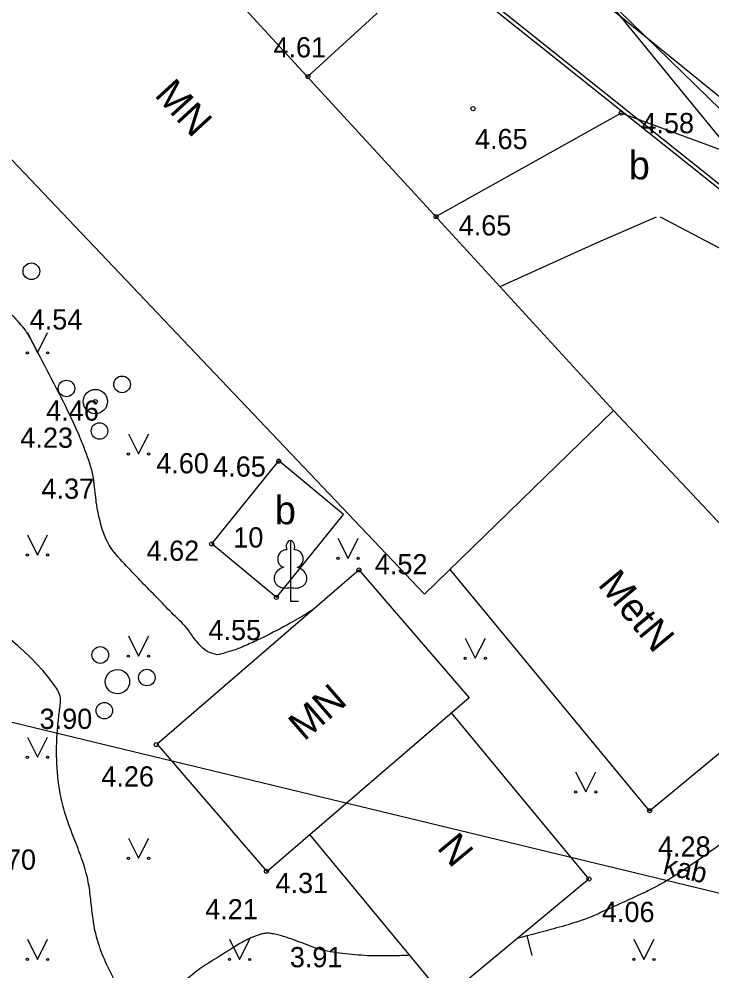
# Model space of a CAD drawing. Extents: x 519536 to 519949, y 326041 to 326519.
# Drawn here: x 519767.04 to 519784.18, y 326282.21 to 326305.75 of the extents above; entities that cross this region are included whole.
import ezdxf

# ---------------------------------------------------------------- set-up
doc = ezdxf.new("R2010")
doc.units = 0
for name, color, linetype in [('APGR_SARK_####_####_#', 7, 'Continuous'), ('BUVE_EKAS_####_####_#', 7, 'Continuous'), ('BUVE_EKAS_BPAL_####_#', 7, 'Continuous'), ('BUVE_EKAS_RAKS_TKST_#', 7, 'Continuous'), ('CELI_CMAL_####_####_#', 7, 'Continuous'), ('CELI_CSEG_####_TKST_#', 7, 'Continuous'), ('ELEK_VADP_ZSPR_####_#', 7, 'Continuous'), ('RELJ_AATZ_####_TKST_#', 7, 'Continuous'), ('RELJ_ELEM_####_####_#', 7, 'Continuous'), ('RELJ_HORZ_PAMT_####_#', 7, 'Continuous'), ('ROBZ_PROJ_####_####_#', 7, 'Continuous'), ('ROBZ_UZMR_####_####_#', 7, 'Continuous'), ('SAKK_KKAN_####_####_#', 7, 'Continuous'), ('SAKT_VADV_PKAB_####_#', 7, 'Continuous'), ('SAKT_VADV_PKAB_TKST_#', 7, 'Continuous'), ('TERT_DIAM_####_TKST_#', 7, 'Continuous'), ('TERT_ELEM_####_####_#', 7, 'Continuous')]:
    doc.layers.add(name, color=color, linetype=linetype)

msp = doc.modelspace()

# ---------------------------------------------------------------- linework, layer by layer
at = {"layer": 'APGR_SARK_####_####_#'}
msp.add_line((519771.5020408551, 326318.57686486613), (519839.50526056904, 326235.2628850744), dxfattribs=at)
at = {"layer": 'BUVE_EKAS_####_####_#'}
for p, q in [((519777.119, 326301.12), (519768.47500000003, 326310.543)), ((519781.74700000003, 326296.075), (519777.119, 326301.12)), ((519781.74700000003, 326296.075), (519780.3550036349, 326294.7205526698)), ((519784.831, 326292.793), (519781.74700000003, 326296.075)), ((519780.3550036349, 326294.7205526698), (519777.076, 326291.53)), ((519770.462, 326287.832), (519775.4511530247, 326292.13029778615)), ((519775.4511530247, 326292.13029778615), (519778.1731530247, 326288.9702977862)), ((519778.1731530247, 326288.9702977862), (519773.184, 326284.672)), ((519773.184, 326284.672), (519770.462, 326287.832))]:
    msp.add_line(p, q, dxfattribs=at)
msp.add_lwpolyline([(519777.076, 326291.53), (519763.07800000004, 326306.251)], dxfattribs=at)
at = {"layer": 'BUVE_EKAS_BPAL_####_#'}
for p, q in [((519782.641, 326286.17600000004), (519777.7031957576, 326292.1402771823)), ((519782.641, 326286.17600000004), (519787.2223480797, 326289.96888215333)), ((519781.13800000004, 326284.489), (519777.73818964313, 326288.5955644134)), ((519777.58200000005, 326281.54500000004), (519774.23402478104, 326285.58895376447)), ((519777.58200000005, 326281.54500000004), (519781.13800000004, 326284.489))]:
    msp.add_line(p, q, dxfattribs=at)
at = {"layer": 'CELI_CMAL_####_####_#'}
for p, q in [((519775.9, 326305.89900000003), (519774.189, 326304.33300000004)), ((519771.808, 326292.775), (519773.47021137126, 326294.8259624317)), ((519775.07021137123, 326293.50296243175), (519773.47021137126, 326294.8259624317)), ((519773.408, 326291.452), (519775.07021137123, 326293.50296243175)), ((519773.408, 326291.452), (519771.808, 326292.775))]:
    msp.add_line(p, q, dxfattribs=at)
for points in [[(519782.901, 326300.86100000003), (519784.67600000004, 326299.934), (519785.84400000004, 326301.988), (519781.93700000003, 326303.43100000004), (519777.358, 326300.87)], [(519778.94100000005, 326299.141), (519781.308, 326300.216), (519782.81100000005, 326300.865)]]:
    msp.add_lwpolyline(points, dxfattribs=at)
at = {"layer": 'ELEK_VADP_ZSPR_####_#'}
for points in [[(519830.368663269, 326246.030227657), (519828.1702429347, 326249.1807123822), (519802.20740225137, 326283.8956003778), (519795.9928819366, 326292.28332314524), (519770.740641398, 326312.4157499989), (519767.54869624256, 326319.6985019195), (519768.2034511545, 326324.3475465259), (519772.3174717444, 326338.8567057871)], [(519780.782, 326304.525), (519771.889, 326311.62200000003)], [(519799.34857528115, 326287.9422010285), (519796.069, 326292.32800000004), (519780.782, 326304.525)]]:
    msp.add_lwpolyline(points, dxfattribs=at)
at = {"layer": 'RELJ_ELEM_####_####_#'}
for centre in [(519774.189, 326304.33300000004), (519778.2711320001, 326303.53878600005), (519781.93700000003, 326303.43100000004), (519777.358, 326300.87), (519768.93000000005, 326296.29600000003), (519773.467, 326294.82200000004), (519771.808, 326292.775), (519775.451, 326292.13), (519773.408, 326291.452), (519770.43700000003, 326287.81200000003), (519782.641, 326286.17600000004), (519773.161, 326284.68), (519781.13800000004, 326284.489)]:
    msp.add_circle(centre, 0.05, dxfattribs=at)
at = {"layer": 'RELJ_HORZ_PAMT_####_#'}
msp.add_line((519779.6058604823, 326283.08196167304), (519779.7280805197, 326282.5971294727), dxfattribs=at)
for points in [[(519768.9482272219, 326293.8646011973), (519768.92128528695, 326294.1106640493), (519768.88297060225, 326294.40952680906), (519768.81333221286, 326294.7013025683), (519768.7033955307, 326295.02040492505), (519768.58319504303, 326295.3343539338), (519768.3089513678, 326295.94770706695), (519767.3925420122, 326297.7320684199), (519767.26196401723, 326297.96806334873), (519767.13499731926, 326298.1455611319), (519766.9909414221, 326298.30928763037), (519766.6741187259, 326298.6102247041), (519766.4738319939, 326298.78710908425), (519766.27167638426, 326298.9603092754), (519765.84971994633, 326299.2824635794), (519764.96896151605, 326299.87938607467), (519764.0832520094, 326300.48417170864), (519763.6505364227, 326300.81361992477), (519763.4447373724, 326300.9927193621), (519763.244, 326301.18), (519762.8425471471, 326301.6241986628), (519762.4992198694, 326302.1146140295), (519762.21454526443, 326302.63803209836), (519761.9836765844, 326303.19307164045), (519761.83115030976, 326303.7023842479), (519761.73341554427, 326304.22113132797), (519761.63275072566, 326305.2671582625), (519761.6394282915, 326305.79893731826), (519761.6535327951, 326306.33087839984), (519761.70018845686, 326307.3942862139), (519761.71876058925, 326307.74637150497)], [(519771.93279070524, 326290.03450955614), (519771.6304535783, 326290.16122137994), (519771.50148263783, 326290.2901018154), (519771.3838236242, 326290.42711000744), (519771.2329594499, 326290.6383997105), (519770.867915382, 326291.0229712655), (519770.49724409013, 326291.4029522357), (519770.1258703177, 326291.7828749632), (519769.75871880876, 326292.16727179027), (519769.3417415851, 326292.6437591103), (519769.21924065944, 326292.8447509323), (519769.1290083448, 326293.060317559), (519769.00844141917, 326293.5134353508), (519768.95440073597, 326293.8101537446), (519768.9482272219, 326293.8646011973)], [(519772.3037991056, 326282.7687551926), (519771.7265414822, 326282.40449786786), (519771.5247364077, 326282.2736022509), (519771.32577707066, 326282.12007177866), (519770.9351707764, 326281.7904900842), (519770.3629491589, 326281.4100049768), (519770.26868459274, 326281.37807846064), (519770.1746338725, 326281.3589304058), (519769.80530474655, 326281.4817614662), (519769.4797521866, 326281.86503770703), (519769.21033155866, 326282.3790786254), (519769.00939822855, 326282.8942037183), (519768.8999230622, 326283.3288329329), (519768.84078488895, 326283.7662808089), (519768.79052642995, 326284.20120891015), (519768.70769040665, 326284.6282788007), (519768.5479745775, 326285.1197754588), (519768.36125570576, 326285.6060716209), (519768.1861727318, 326286.0971767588), (519768.06136459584, 326286.60310034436), (519768.00299225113, 326288.2795758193), (519768.04188478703, 326288.62647923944), (519768.06447333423, 326288.79963326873), (519768.0680781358, 326288.97267270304), (519767.9178786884, 326289.2775001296), (519765.26791854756, 326291.6173466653), (519765.17379177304, 326291.6835162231), (519764.88886906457, 326291.7177816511), (519764.5102364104, 326291.0977889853), (519763.1472943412, 326287.19180446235), (519763.086313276, 326286.0097349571), (519763.4077698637, 326284.9752966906), (519763.89341618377, 326283.4690026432), (519764.06192513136, 326282.7101966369), (519764.0542015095, 326281.93201949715), (519763.80013137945, 326281.1633634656), (519763.55880576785, 326280.79163469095), (519763.40573596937, 326280.6105001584), (519763.32062002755, 326280.52131286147), (519763.22960080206, 326280.4331207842), (519762.8743324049, 326280.22632388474), (519762.51153899, 326280.1989100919), (519761.7900461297, 326280.3313768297), (519761.59721181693, 326280.3721994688), (519761.40436009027, 326280.4318008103), (519761.21165912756, 326280.48302410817), (519761.0192771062, 326280.4987126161), (519759.23806750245, 326279.99160951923), (519758.9520704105, 326279.8355438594), (519758.68201619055, 326279.66972863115), (519758.41540199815, 326279.5052413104), (519758.13972498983, 326279.3531593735), (519756.45872597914, 326278.5629404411), (519754.74648434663, 326277.84880748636), (519754.5322637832, 326277.79851086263), (519754.0413100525, 326277.46207363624), (519753.6762339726, 326277.0319883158), (519753.3405213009, 326276.59453688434), (519752.75223708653, 326275.69236061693), (519752.2665592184, 326274.7451946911), (519751.8735895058, 326273.74268896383), (519751.57436674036, 326272.7572303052), (519751.3630077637, 326271.755380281), (519751.1902698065, 326270.21862873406)], [(519774.30212140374, 326291.1403742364), (519774.20817665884, 326291.0841860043), (519773.9803627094, 326290.94690071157), (519773.74973964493, 326290.81407985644), (519773.0794785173, 326290.4615372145), (519772.73671818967, 326290.3007069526), (519772.56252624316, 326290.22564805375), (519772.3861152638, 326290.1547298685), (519772.1596644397, 326290.0861544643), (519771.93323377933, 326290.03452825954), (519771.93279070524, 326290.03450955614)], [(519786.2017961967, 326286.52632436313), (519786.09832418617, 326286.4692661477), (519785.99075401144, 326286.41957294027), (519785.88364397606, 326286.36927084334), (519785.78155238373, 326286.3103859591), (519785.2662393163, 326285.9585843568), (519784.79090867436, 326285.6261180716), (519784.3176832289, 326285.2908254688), (519783.60357046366, 326284.79307712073), (519783.48329929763, 326284.7116862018), (519783.3625137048, 326284.6309428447), (519782.98794787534, 326284.4028738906), (519782.5996328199, 326284.1988032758), (519782.2030383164, 326284.010043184), (519781.8036341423, 326283.82790579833), (519781.5408067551, 326283.7084944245), (519781.3163471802, 326283.60582770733), (519780.19742068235, 326283.23858751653), (519779.36156973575, 326283.0182995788)], [(519776.7062727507, 326282.60277381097), (519776.5027566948, 326282.5941124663), (519776.299135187, 326282.58865602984), (519776.09554168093, 326282.5859240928), (519775.89210963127, 326282.5854362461), (519775.5830794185, 326282.59642601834), (519775.2741894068, 326282.62150404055), (519774.9687310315, 326282.65571572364), (519774.66504914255, 326282.70404220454), (519774.41456953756, 326282.76814304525), (519774.16767239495, 326282.8578403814), (519773.9213618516, 326282.95419523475), (519773.6726420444, 326283.03826862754), (519773.54126718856, 326283.07933466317), (519773.4087875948, 326283.1150522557), (519773.2760518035, 326283.13944821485), (519773.20985300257, 326283.14553395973), (519773.1768422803, 326283.14672211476), (519773.1439083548, 326283.14654934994), (519773.050292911, 326283.1305543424), (519772.9572017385, 326283.0997170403), (519772.86462869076, 326283.06717382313), (519772.7748411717, 326283.0298551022), (519772.68411011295, 326282.98580293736), (519772.59450583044, 326282.9401070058), (519772.41991509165, 326282.8408592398), (519772.3037991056, 326282.7687551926)]]:
    msp.add_spline(points, degree=3, dxfattribs=at)
at = {"layer": 'ROBZ_PROJ_####_####_#'}
msp.add_line((519793.42600000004, 326294.6769999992), (519766.63399999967, 326320.8839999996), dxfattribs=at)
at = {"layer": 'ROBZ_UZMR_####_####_#'}
msp.add_line((519766.63399999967, 326320.8839999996), (519793.42600000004, 326294.6769999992), dxfattribs=at)
at = {"layer": 'SAKK_KKAN_####_####_#'}
for p, q in [((519773.07, 326313.014), (519782.058, 326305.712)), ((519782.058, 326305.712), (519794.06700000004, 326295.955))]:
    msp.add_line(p, q, dxfattribs=at)
at = {"layer": 'SAKT_VADV_PKAB_####_#'}
msp.add_lwpolyline([(519822.5716386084, 326274.90377568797), (519730.8236856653, 326297.05955857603)], dxfattribs=at)
at = {"layer": 'TERT_ELEM_####_####_#'}
for p, q in [((519767.25, 326298), (519767.5, 326297.5)), ((519767.5, 326297.5), (519767.75, 326298)), ((519769.75, 326295.5), (519770, 326295)), ((519770, 326295), (519770.25, 326295.5)), ((519767.25, 326293), (519767.5, 326292.5)), ((519767.5, 326292.5), (519767.75, 326293)), ((519774.9314085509, 326292.91795918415), (519775.1814085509, 326292.41795918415)), ((519775.1814085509, 326292.41795918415), (519775.4314085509, 326292.91795918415)), ((519773.75700000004, 326291.7049923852), (519773.75700000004, 326291.358)), ((519773.75700000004, 326291.358), (519773.95700000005, 326291.358)), ((519769.75, 326290.5), (519770, 326290)), ((519770, 326290), (519770.25, 326290.5)), ((519778.0786365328, 326290.4481587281), (519778.3286365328, 326289.9481587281)), ((519778.3286365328, 326289.9481587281), (519778.5786365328, 326290.4481587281)), ((519767.25, 326288), (519767.5, 326287.5)), ((519767.5, 326287.5), (519767.75, 326288)), ((519780.8082180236, 326287.14139886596), (519781.0582180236, 326286.64139886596)), ((519781.0582180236, 326286.64139886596), (519781.3082180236, 326287.14139886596)), ((519769.75, 326285.5), (519770, 326285)), ((519770, 326285), (519770.25, 326285.5)), ((519767.25, 326283), (519767.5, 326282.5)), ((519767.5, 326282.5), (519767.75, 326283)), ((519772.25, 326283), (519772.5, 326282.5)), ((519772.5, 326282.5), (519772.75, 326283)), ((519782.25, 326283), (519782.5, 326282.5)), ((519782.5, 326282.5), (519782.75, 326283))]:
    msp.add_line(p, q, dxfattribs=at)
for points in [[(519773.75700000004, 326292.8579988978), (519773.75700000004, 326291.7049923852)], [(519773.84655848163, 326292.6256060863), (519773.8455632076, 326292.626518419)]]:
    msp.add_lwpolyline(points, dxfattribs=at)
for centre, radius in [((519767.34848458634, 326299.51684871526), 0.2066127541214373), ((519767.2497200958, 326297.49954969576), 0.02800000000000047), ((519767.7497200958, 326297.49954969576), 0.02630589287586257), ((519769.59148458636, 326296.7208487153), 0.2066127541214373), ((519768.21586157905, 326296.61984797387), 0.20413472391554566), ((519768.93000000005, 326296.29600000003), 0.3006396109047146), ((519769.03329362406, 326295.56845055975), 0.20454262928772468), ((519769.7497200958, 326294.99954969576), 0.02800000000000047), ((519770.2497200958, 326294.99954969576), 0.02630589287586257), ((519767.2497200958, 326292.49954969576), 0.02800000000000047), ((519767.7497200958, 326292.49954969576), 0.02630589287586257), ((519774.9311286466, 326292.41750887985), 0.02800000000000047), ((519775.4311286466, 326292.41750887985), 0.02630589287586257), ((519769.0531512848, 326290.02848458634), 0.2066127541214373), ((519769.7497200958, 326289.99954969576), 0.02800000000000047), ((519770.2497200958, 326289.99954969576), 0.02630589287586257), ((519778.07835662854, 326289.94770842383), 0.02800000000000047), ((519778.57835662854, 326289.94770842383), 0.02630589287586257), ((519769.478, 326289.367), 0.3006396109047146), ((519770.2055494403, 326289.47029362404), 0.20454262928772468), ((519769.1541520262, 326288.65286157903), 0.20413472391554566), ((519767.2497200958, 326287.49954969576), 0.02800000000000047), ((519767.7497200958, 326287.49954969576), 0.02630589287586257), ((519780.80793811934, 326286.64094856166), 0.02800000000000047), ((519781.30793811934, 326286.64094856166), 0.02630589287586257), ((519769.7497200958, 326284.99954969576), 0.02800000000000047), ((519770.2497200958, 326284.99954969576), 0.02630589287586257), ((519767.2497200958, 326282.49954969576), 0.02800000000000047), ((519767.7497200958, 326282.49954969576), 0.02630589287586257), ((519772.2497200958, 326282.49954969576), 0.02800000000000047), ((519772.7497200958, 326282.49954969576), 0.02630589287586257), ((519782.2497200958, 326282.49954969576), 0.02800000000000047), ((519782.7497200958, 326282.49954969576), 0.02630589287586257)]:
    msp.add_circle(centre, radius, dxfattribs=at)
for centre, major_axis, ratio, start_param, end_param in [((519773.75740043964, 326292.7080684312), (-2.411082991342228e-17, -0.1499315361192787), 0.7071067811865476, 3.1453697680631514, 5.287484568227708), ((519773.7565995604, 326292.7080684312), (4.2472147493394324e-17, -0.1499315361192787), 0.7071067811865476, 0.9957007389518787, 3.137815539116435), ((519773.6287092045, 326292.4132030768), (-0.03873231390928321, -0.21240300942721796), 0.8613228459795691, 3.141592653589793, 6.283185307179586), ((519773.88529079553, 326292.4132030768), (0.038732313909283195, -0.21240300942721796), 0.8613228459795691, 0, 3.141592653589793), ((519773.66744151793, 326291.95091417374), (0.306817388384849, 0.0951133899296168), 0.8144450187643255, 1.5707963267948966, 4.752014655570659), ((519773.8465584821, 326291.95091417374), (-0.30681738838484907, 0.09511338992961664), 0.8144450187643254, 1.5311706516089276, 4.71238898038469)]:
    msp.add_ellipse(centre, major_axis=major_axis, ratio=ratio, start_param=start_param, end_param=end_param, dxfattribs=at)

# ---------------------------------------------------------------- texts
at = {"layer": 'BUVE_EKAS_RAKS_TKST_#'}
for s, rotation, p in [('MN', 312.5310907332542, (519770.37162944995, 326303.8638410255)), ('MetN', 309.6212388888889, (519781.33878672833, 326291.7645908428)), ('MN', 40.95065555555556, (519774.09500000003, 326287.88300000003)), ('N', 309.6212388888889, (519777.359, 326285.25200000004))]:
    msp.add_text(s, height=0.7, rotation=rotation, dxfattribs=at).set_placement(p)
at = {"layer": 'CELI_CSEG_####_TKST_#'}
for p in [(519782.12475356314, 326301.79174366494), (519773.3697045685, 326293.26138256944)]:
    msp.add_text('b', height=0.7, dxfattribs=at).set_placement(p)
at = {"layer": 'RELJ_AATZ_####_TKST_#'}
for s, p in [('4.61', (519773.337, 326304.80600000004)), ('4.58', (519782.43700000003, 326302.93100000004)), ('4.65', (519778.321132, 326302.53878600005)), ('4.65', (519777.917, 326300.403)), ('4.54', (519767.30700000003, 326298.077)), (' 4.46', (519767.53, 326295.82300000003)), ('4.23', (519767.07700000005, 326295.152)), (' 4.60', (519770.25200000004, 326294.521)), ('4.65', (519771.846, 326294.439)), (' 4.37', (519767.41400000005, 326293.892)), ('4.62', (519770.19800000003, 326292.358)), ('4.52', (519775.84400000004, 326292.02300000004)), ('4.55', (519771.72900000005, 326290.396)), ('3.90', (519767.553, 326288.2)), ('4.26', (519769.079, 326286.776)), ('4.28', (519782.847, 326285.042)), (' 3.70', (519765.976, 326284.71900000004)), (' 4.31', (519773.201, 326284.141)), ('4.21', (519771.64900000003, 326283.49100000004)), ('4.06', (519781.46, 326283.425)), ('3.91', (519773.74100000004, 326282.30700000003))]:
    msp.add_text(s, height=0.5, dxfattribs=at).set_placement(p)
at = {"layer": 'SAKT_VADV_PKAB_TKST_#'}
msp.add_text('kab', height=0.5, rotation=346.4238267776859, dxfattribs=at).set_placement((519782.94457031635, 326284.62744224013))
at = {"layer": 'TERT_DIAM_####_TKST_#'}
msp.add_text(' 10', height=0.5, dxfattribs=at).set_placement((519772.157, 326292.686))

doc.saveas('drawing.dxf')
